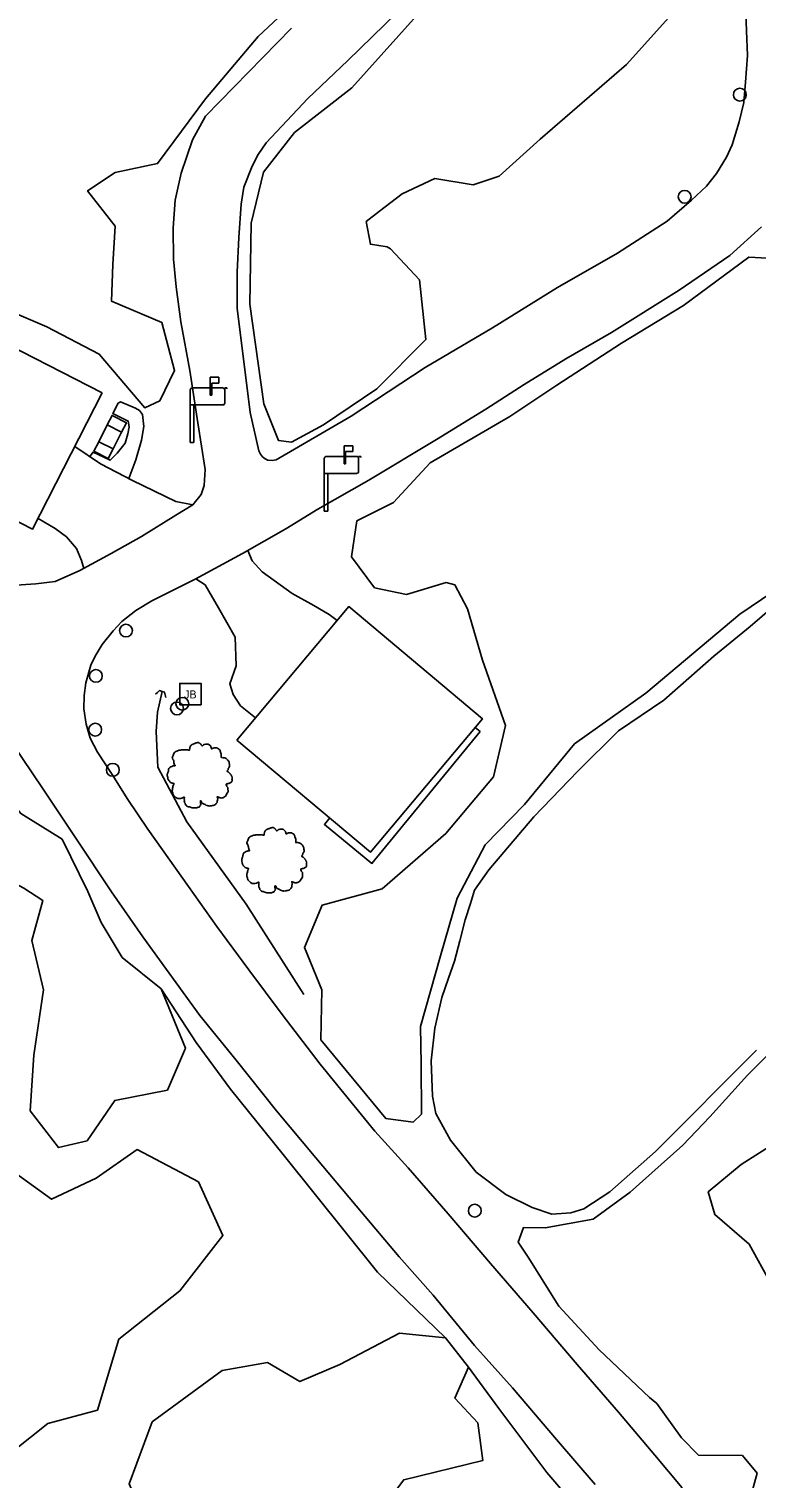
# Model space of a CAD drawing. Extents: x 2160437 to 2172832, y 205694 to 212444.
# Drawn here: x 2171429.7 to 2171600, y 207128.5 to 207468 of the extents above; entities that cross this region are included whole.
import ezdxf

# ---------------------------------------------------------------- set-up
doc = ezdxf.new("R2010")
doc.units = 0
for name, color, linetype in [('Default', 7, 'Continuous'), ('RD_EX_Bldg', 7, 'Continuous'), ('RD_EX_BldgApp', 7, 'Continuous'), ('RD_EX_Conc', 7, 'Continuous'), ('RD_EX_DR_Culvert', 7, 'Continuous'), ('RD_EX_DR_Inlet', 7, 'Continuous'), ('RD_EX_Driveway', 7, 'Continuous'), ('RD_EX_H2O_Ditch', 7, 'Continuous'), ('RD_EX_H2O_Pond', 7, 'Continuous'), ('RD_EX_Road', 7, 'Continuous'), ('RD_EX_Road_Post', 7, 'Continuous'), ('RD_EX_VEG', 7, 'Continuous'), ('RD_EX_VEG_ShrubLine', 7, 'Continuous'), ('RD_EX_VEG_TreeLine', 7, 'Continuous')]:
    doc.layers.add(name, color=color, linetype=linetype)

# ---------------------------------------------------------------- blocks, each defined once
blk = doc.blocks.new('CB')
at = {"layer": 'Default'}
blk.add_lwpolyline([(0.036, -0.042), (0.018, -0.031), (0, -0.021), (0, 0), (0, 0.021), (0.018, 0.031), (0.036, 0.042)], dxfattribs=at)
blk = doc.blocks.new('POST')
at = {"layer": 'Default'}
for start, end in [(90, 270), (270, 90)]:
    blk.add_arc((0, 0), 0.0417, start, end, dxfattribs=at)
blk = doc.blocks.new('T2')
at = {"layer": 'RD_EX_VEG'}
for points in [[(0.05, 7.21), (-0.25, 7.24), (-0.57, 7.14), (-0.82, 7.04), (-1.05, 6.96), (-1.27, 6.86), (-1.57, 6.69), (-1.8, 6.49), (-1.92, 6.24), (-1.97, 6.01), (-2.02, 5.74), (-2.02, 5.56), (-2.15, 5.54), (-2.3, 5.56), (-2.55, 5.64), (-2.8, 5.64), (-3.05, 5.64), (-3.4, 5.61), (-3.75, 5.61), (-4.02, 5.56), (-4.35, 5.51), (-4.72, 5.39), (-5.07, 5.26), (-5.37, 5.01), (-5.62, 4.54), (-5.75, 4.19), (-5.9, 3.94), (-5.75, 3.49), (-5.57, 3.14), (-5.55, 2.94), (-5.47, 2.52), (-5.37, 2.29), (-5.25, 2.09), (-5.32, 2.07), (-5.7, 2.02), (-6, 1.92), (-6.42, 1.69), (-6.64, 1.47), (-6.74, 1.14), (-6.77, 0.79), (-6.87, 0.59), (-6.94, 0.32), (-6.97, 0.24), (-7.02, -0.08), (-6.92, -0.53), (-6.89, -0.88), (-6.77, -1.11), (-6.62, -1.28), (-6.44, -1.53), (-6.05, -1.76), (-5.72, -1.86), (-5.52, -1.88), (-5.7, -2.38), (-5.75, -2.73), (-5.87, -3.13), (-5.87, -3.21), (-5.92, -3.68), (-5.77, -4.01), (-5.7, -4.38), (-5.52, -4.61), (-5.25, -4.91), (-4.92, -5.13), (-4.42, -5.26), (-4.02, -5.23), (-3.45, -5.06), (-3.2, -4.98), (-3.22, -5.16), (-3.2, -5.53), (-3.2, -5.96), (-3.05, -6.28), (-2.95, -6.56), (-2.8, -6.81), (-2.47, -7.03), (-2.07, -7.11), (-1.65, -7.26), (-1.2, -7.33), (-0.7, -7.36), (-0.1, -7.21), (0.18, -7.08), (0.28, -6.91), (0.48, -6.53), (0.43, -6.31), (0.45, -5.71), (0.55, -5.88), (0.73, -6.23), (1.23, -6.53), (1.63, -6.71), (2.1, -6.86), (2.4, -6.93), (2.88, -6.86), (3.25, -6.78), (3.63, -6.66), (3.93, -6.38), (4.1, -6.11), (4.15, -5.83), (4.23, -5.46), (4.28, -5.28)], [(4.28, -5.28), (4.2, -5.11), (4.15, -4.86), (4.23, -4.88), (4.4, -4.93), (4.68, -5.06), (4.9, -5.13), (5.23, -5.11), (5.5, -5.01), (5.95, -4.73), (6.22, -4.26), (6.5, -3.86), (6.57, -3.53), (6.52, -3.31), (6.5, -2.81), (6.3, -2.56), (6.25, -2.43), (6.15, -2.03), (6.22, -1.98), (6.5, -1.93), (6.87, -1.81), (7.15, -1.68), (7.37, -1.51), (7.45, -1.28), (7.42, -0.88), (7.47, -0.48), (7.4, -0.33), (7.3, -0.18), (7.22, 0.02), (7.07, 0.17), (6.97, 0.32), (6.87, 0.42), (6.75, 0.57), (6.57, 0.69), (6.42, 0.74), (6.37, 0.89), (6.52, 1.09), (6.57, 1.19), (6.6, 1.42), (6.82, 1.77), (6.87, 2.17), (6.82, 2.59), (6.77, 2.87), (6.62, 3.14), (6.42, 3.39), (6.3, 3.56), (6.12, 3.69), (5.8, 3.81), (5.55, 3.86), (5.2, 3.86), (5, 3.91), (5.03, 3.96), (5.03, 4.11), (5.03, 4.39), (4.95, 4.84), (4.8, 5.34), (4.8, 5.36), (4.7, 5.61), (4.48, 5.81), (4.3, 5.91), (4.1, 6.04), (3.85, 6.06), (3.55, 6.06), (3.28, 6.01), (3.08, 5.91), (2.9, 5.79), (2.83, 5.94), (2.73, 6.24), (2.68, 6.39), (2.53, 6.56), (2.3, 6.76), (1.85, 6.89), (1.23, 6.81), (0.93, 6.61), (0.78, 6.44), (0.73, 6.56), (0.53, 6.76), (0.43, 6.94), (0.25, 7.06), (0.1, 7.16), (0, 7.21)]]:
    blk.add_spline(points, degree=3, dxfattribs=at)

msp = doc.modelspace()

# ---------------------------------------------------------------- linework, layer by layer
at = {"layer": 'RD_EX_Bldg'}
for points in [[(2171446.83, 207382.74), (2171430.51, 207350.85), (2171389.43, 207371.87), (2171405.74, 207403.76)], [(2171478.36, 207301.4), (2171504.58, 207332.66), (2171535.89, 207306.4), (2171509.68, 207275.14)]]:
    msp.add_lwpolyline(points, close=True, dxfattribs=at)
at = {"layer": 'RD_EX_BldgApp'}
for p, q in [((2171472.07, 207386.39), (2171474.13, 207386.39)), ((2171472.07, 207382.2), (2171472.07, 207386.39)), ((2171474.13, 207385.04), (2171472.45, 207385.04)), ((2171472.45, 207385.04), (2171472.45, 207382.2)), ((2171474.13, 207386.39), (2171474.13, 207385.04)), ((2171467.43, 207379.91), (2171467.43, 207383.41)), ((2171467.93, 207383.91), (2171475, 207383.91)), ((2171472.45, 207382.2), (2171472.07, 207382.2)), ((2171475.5, 207383.41), (2171475.5, 207383.91)), ((2171475.5, 207383.91), (2171476, 207383.91)), ((2171475.5, 207383.41), (2171475.5, 207380.41)), ((2171476, 207383.91), (2171476, 207383.66)), ((2171467.43, 207379.91), (2171467.43, 207371.09)), ((2171475, 207379.91), (2171467.43, 207379.91)), ((2171468.27, 207379.91), (2171468.27, 207371.09)), ((2171467.43, 207371.09), (2171468.27, 207371.09)), ((2171503.46, 207370.34), (2171505.51, 207370.34)), ((2171503.46, 207366.15), (2171503.46, 207370.34)), ((2171505.51, 207368.99), (2171503.84, 207368.99)), ((2171503.84, 207368.99), (2171503.84, 207366.15)), ((2171505.51, 207370.34), (2171505.51, 207368.99)), ((2171498.81, 207363.86), (2171498.81, 207367.36)), ((2171499.31, 207367.86), (2171506.38, 207367.86)), ((2171503.84, 207366.15), (2171503.46, 207366.15)), ((2171506.88, 207367.36), (2171506.88, 207367.86)), ((2171506.88, 207367.86), (2171507.38, 207367.86)), ((2171506.88, 207367.36), (2171506.88, 207364.36)), ((2171507.38, 207367.86), (2171507.38, 207367.61)), ((2171498.81, 207363.86), (2171498.81, 207355.04)), ((2171506.38, 207363.86), (2171498.81, 207363.86)), ((2171499.65, 207363.86), (2171499.65, 207355.04)), ((2171498.81, 207355.04), (2171499.65, 207355.04))]:
    msp.add_line(p, q, dxfattribs=at)
for points in [[(2171447.98, 207375.24), (2171451.35, 207373.53), (2171449.37, 207369.61), (2171445.99, 207371.31)], [(2171447.98, 207375.24), (2171451.35, 207373.53), (2171452.47, 207375.74), (2171449.1, 207377.45)], [(2171445.99, 207371.31), (2171449.37, 207369.61), (2171448.24, 207367.38), (2171444.87, 207369.09)]]:
    msp.add_lwpolyline(points, close=True, dxfattribs=at)
for points in [[(2171534.17, 207304.34), (2171535.33, 207303.39)], [(2171535.33, 207303.39), (2171509.99, 207272.49), (2171498.85, 207281.63), (2171500.11, 207283.17)]]:
    msp.add_lwpolyline(points, dxfattribs=at)
for centre, start, end in [((2171467.93, 207383.41), 90, 180), ((2171475, 207383.41), 360, 90), ((2171475, 207380.41), 270, 0), ((2171499.31, 207367.36), 90, 180), ((2171506.38, 207367.36), 360, 90), ((2171506.38, 207364.36), 270, 0)]:
    msp.add_arc(centre, 0.5, start, end, dxfattribs=at)
at = {"layer": 'RD_EX_Conc'}
msp.add_lwpolyline([(2171443.93, 207367.81), (2171444.68, 207368.89), (2171448.7, 207366.96), (2171450.31, 207368.59), (2171452.18, 207370.97), (2171452.83, 207373.17), (2171453.13, 207374.77), (2171452.89, 207376.13), (2171449.26, 207377.88), (2171450.51, 207380.37), (2171451.07, 207380.65), (2171454.58, 207379.13), (2171455.51, 207378.6), (2171456.22, 207377.64), (2171456.57, 207374.87), (2171455.99, 207371.67), (2171454.68, 207367.04), (2171453.04, 207362.65)], dxfattribs=at)
at = {"layer": 'RD_EX_DR_Inlet'}
msp.add_line((2171469.96, 207309.68), (2171469.96, 207314.68), dxfattribs=at)
msp.add_lwpolyline([(2171469.96, 207309.68), (2171469.96, 207314.68), (2171464.96, 207314.68), (2171464.96, 207309.68)], close=True, dxfattribs=at)
at = {"layer": 'RD_EX_Driveway'}
for points in [[(2171468, 207356.5), (2171464.04, 207357.32), (2171453.93, 207362.18), (2171446.4, 207366.11), (2171440.42, 207370.22)], [(2171442.48, 207341.6), (2171441.99, 207343.51), (2171440.75, 207346.25), (2171438.43, 207349.03), (2171435.78, 207350.98), (2171431.78, 207353.33)], [(2171480.91, 207345.79), (2171481.91, 207343.38), (2171484.26, 207340.82), (2171491.32, 207335.75), (2171496.35, 207332.93), (2171499.95, 207330.83), (2171501.89, 207329.45)], [(2171468.72, 207339.2), (2171470.95, 207337.74), (2171474.07, 207332.39), (2171477.92, 207325.52), (2171478.16, 207318.83), (2171476.71, 207314.57), (2171477.48, 207312.09), (2171479.17, 207309.43), (2171482.74, 207306.62)]]:
    msp.add_lwpolyline(points, dxfattribs=at)
at = {"layer": 'RD_EX_H2O_Ditch'}
msp.add_lwpolyline([(2171494.01, 207241.77), (2171480.53, 207262.98), (2171466.6, 207282.21), (2171459.84, 207295.05), (2171459.41, 207303.4), (2171459.79, 207307.92), (2171460.82, 207312.8)], dxfattribs=at)
at = {"layer": 'RD_EX_H2O_Pond'}
msp.add_lwpolyline([(2171600.08, 207228.72), (2171576.41, 207204.98), (2171565.72, 207195.53), (2171559.63, 207191.57), (2171556.56, 207190.65), (2171552.16, 207190.34), (2171547.5, 207191.92), (2171541.37, 207194.94), (2171534.39, 207200.19), (2171528.37, 207207.63), (2171524.95, 207213.88), (2171524.18, 207217.94), (2171523.87, 207226.21), (2171524.77, 207233.92), (2171526.4, 207241.09), (2171527.96, 207245.6), (2171529.36, 207249.63), (2171530.57, 207254.36), (2171531.83, 207259.31), (2171533.05, 207263.07), (2171534, 207266.23), (2171537.36, 207270.99), (2171547.92, 207283.45), (2171558.24, 207294.08), (2171567.74, 207303.58), (2171578.35, 207310.73), (2171590.09, 207321.02), (2171598.64, 207328.01), (2171607.01, 207335.28)], dxfattribs=at)
at = {"layer": 'RD_EX_Road'}
for points in [[(2171530.12, 207485.76), (2171504.37, 207460.59), (2171495, 207451.72), (2171485.18, 207441.31), (2171483.34, 207438.63), (2171481.97, 207435.88), (2171480, 207430.92), (2171479.37, 207426.92), (2171478.78, 207419.12), (2171478.43, 207411.02), (2171478.43, 207402.57), (2171481.45, 207378.12), (2171483.5, 207369.16), (2171483.88, 207368.36), (2171484.37, 207367.74), (2171484.95, 207367.3), (2171485.58, 207367.01), (2171486.66, 207366.88), (2171487.57, 207367.03), (2171505.1, 207377.3), (2171522.43, 207388.66), (2171538.23, 207397.95), (2171553.51, 207407.44), (2171567.55, 207415.49), (2171579.13, 207423), (2171584.83, 207427.88), (2171588.34, 207431.21), (2171590.75, 207434.17), (2171593.07, 207438), (2171594.38, 207440.85), (2171596.06, 207446.22), (2171597.1, 207450.74), (2171597.49, 207455.51), (2171598, 207461.81), (2171597.74, 207467.54), (2171597.55, 207473.95)], [(2171491.13, 207468.22), (2171471.04, 207447.57), (2171467.98, 207442.02), (2171465.33, 207434.23), (2171463.92, 207427.9), (2171463.46, 207421.43), (2171463.53, 207414.08), (2171464.14, 207407.58), (2171465.2, 207399.38), (2171467.3, 207388), (2171469.2, 207375.75), (2171470.93, 207364.82), (2171470.71, 207361.04), (2171469.98, 207358.96), (2171468.02, 207356.51), (2171464.05, 207354.12), (2171456.02, 207349.08), (2171448.87, 207345.08), (2171441.55, 207341.09), (2171435.77, 207338.57), (2171431.25, 207338), (2171425.5, 207337.6)], [(2171582.69, 207126.23), (2171576.25, 207133.86), (2171576.25, 207133.86), (2171567.77, 207143.91), (2171558.07, 207155.07), (2171547.77, 207167.18), (2171537.81, 207178.8), (2171527.84, 207190.36), (2171518.52, 207201.18), (2171510.7, 207209.78), (2171497.84, 207225.49), (2171488.97, 207237.12), (2171481.14, 207247.53), (2171473.65, 207257.73), (2171465.68, 207268.94), (2171457.52, 207280.56), (2171452.81, 207287.5), (2171449.12, 207293.34), (2171445.67, 207298.53), (2171444.02, 207301.88), (2171443.01, 207305.11), (2171442.53, 207308.71), (2171442.54, 207311.81), (2171442.97, 207314.83), (2171444.13, 207318.97), (2171445.12, 207321.06), (2171446.83, 207323.8), (2171449.35, 207327.01), (2171451.44, 207329.17), (2171454.66, 207331.75), (2171458.45, 207334.04), (2171468.59, 207339.13), (2171479.69, 207345.09), (2171489.79, 207350.88), (2171497.29, 207355.48), (2171509.27, 207362.26), (2171525.16, 207371.83), (2171536.66, 207378.91), (2171545.67, 207384.69), (2171555.39, 207390.75), (2171566.14, 207396.86), (2171581.99, 207406.82), (2171593.86, 207414.95), (2171601.3, 207421.64)], [(2171425.53, 207300.93), (2171433.01, 207289.87), (2171440.6, 207278.38), (2171449, 207265.85), (2171456.3, 207255.33), (2171469.67, 207236.87), (2171469.67, 207236.87), (2171478.22, 207226.43), (2171487.63, 207214.54), (2171496.84, 207203.54), (2171506.3, 207192.26), (2171516.39, 207180.35), (2171524.32, 207171.37), (2171534, 207159.58), (2171542.93, 207149.63), (2171553.25, 207137.55), (2171562.31, 207126.95)]]:
    msp.add_lwpolyline(points, dxfattribs=at)
at = {"layer": 'RD_EX_VEG_ShrubLine'}
for points in [[(2171460.58, 207243.08), (2171468.81, 207230.57), (2171476.9, 207219.57), (2171489.22, 207204.29), (2171511.28, 207176.71), (2171527.21, 207161.36)], [(2171532.6, 207154.5), (2171539.69, 207144.82), (2171550.96, 207129.8), (2171561.12, 207117.96)]]:
    msp.add_lwpolyline(points, dxfattribs=at)
at = {"layer": 'RD_EX_VEG_TreeLine'}
for points in [[(2171510.74, 207491.92), (2171483.32, 207466.26), (2171471.02, 207451.61), (2171459.78, 207436.47), (2171449.85, 207434.41), (2171443.38, 207430.11), (2171449.82, 207421.8), (2171449.33, 207412.83), (2171449, 207404.22), (2171460.81, 207399.21), (2171463.78, 207388.01), (2171460.28, 207380.85), (2171456.77, 207379.26), (2171446.12, 207391.82), (2171433.84, 207398.19), (2171416.8, 207405.52)], [(2171583.1, 207474.56), (2171569.67, 207459.71), (2171549.43, 207442.21), (2171539.84, 207433.52), (2171533.72, 207431.46), (2171524.75, 207432.95), (2171517.1, 207429.36), (2171511.79, 207425.3), (2171508.64, 207422.89), (2171509.64, 207417.55), (2171513.54, 207416.98), (2171514.34, 207416.51), (2171521.14, 207409.22), (2171522.63, 207395.23), (2171511.11, 207383.66), (2171498.63, 207375.29), (2171491.16, 207371.21), (2171488.09, 207371.6), (2171484.64, 207380.2), (2171481.36, 207403.55), (2171481.74, 207422.47), (2171484.61, 207434.45), (2171491.82, 207443.73), (2171505.27, 207454.2), (2171523.17, 207474.1)], [(2171609.03, 207339.53), (2171596.22, 207330.89), (2171574.2, 207312.38), (2171557.45, 207300.49), (2171545.73, 207286.28), (2171536.54, 207276.89), (2171529.97, 207264.38), (2171526.07, 207250.83), (2171521.41, 207234.29), (2171521.53, 207225.5), (2171521.62, 207213.78), (2171519.62, 207211.86), (2171513.23, 207212.76), (2171498.02, 207231.14), (2171498.26, 207242.91), (2171494.18, 207252.81), (2171498.32, 207262.69), (2171512.39, 207266.57), (2171527.29, 207279.53), (2171538.46, 207292.77), (2171541.25, 207304.79), (2171535.92, 207320.14), (2171532.4, 207332.13), (2171529.41, 207337.77), (2171527.41, 207338.28), (2171518.12, 207335.54), (2171510.6, 207337.08), (2171505.21, 207344.33), (2171506.46, 207352.79), (2171515.03, 207357.08), (2171523.65, 207366.32), (2171542.29, 207377.24), (2171553.28, 207384.58), (2171568.44, 207394.36), (2171582.98, 207403.21), (2171598.26, 207414.57), (2171607.07, 207414.07)], [(2171600.22, 207129.6), (2171596.78, 207133.75), (2171586.48, 207133.89), (2171582.56, 207137.94), (2171576.74, 207145.96), (2171575.06, 207147.33), (2171563.22, 207158.55), (2171553.81, 207168.76), (2171546.57, 207180.22), (2171544.24, 207183.75), (2171545.52, 207187.23), (2171550.61, 207187.13), (2171561.8, 207189.15), (2171570.5, 207195.51), (2171582.83, 207206.52), (2171589.18, 207213.11), (2171597.95, 207222.87), (2171605.48, 207230.42)], [(2171361.09, 207126.77), (2171368.51, 207138), (2171360.06, 207150.55), (2171365.9, 207162.08), (2171372.51, 207165.99), (2171370.84, 207177.45), (2171376.25, 207186.19), (2171389.35, 207197.7), (2171406.4, 207195.73), (2171416.35, 207201.1), (2171426.52, 207199.95), (2171434.93, 207193.83), (2171445.42, 207198.74), (2171455.02, 207205.44), (2171469.39, 207197.86), (2171475.1, 207185.36), (2171464.96, 207172.34), (2171450.68, 207161.05), (2171445.69, 207144.43), (2171434.1, 207141.31), (2171426, 207134.88), (2171414.8, 207127.95)], [(2171604.83, 207207.24), (2171596.52, 207201.97), (2171588.78, 207195.59), (2171590.35, 207190.23), (2171598.4, 207183.32), (2171603.44, 207174.05)], [(2171598.12, 207122.01), (2171600.22, 207129.6)]]:
    msp.add_lwpolyline(points, dxfattribs=at)
for points in [[(2171424.01, 207269.1), (2171415.62, 207270.61), (2171408.92, 207279.04), (2171408.68, 207286.42), (2171413.09, 207293.69), (2171419.86, 207294), (2171427.74, 207284.17), (2171437.41, 207278.22), (2171443.41, 207265.95), (2171446.56, 207258.62), (2171451.48, 207250.48), (2171460.58, 207243.08), (2171466.29, 207229.23), (2171462.09, 207219.4), (2171449.74, 207216.96), (2171443.27, 207207.53), (2171436.54, 207205.92), (2171429.91, 207214.53), (2171430.79, 207227.6), (2171433.03, 207242.92), (2171430.31, 207254.44), (2171432.92, 207263.82), (2171428.48, 207266.72), (2171425.56, 207268.28)], [(2171474.7, 207108.12), (2171459.43, 207112.36), (2171453.09, 207127.15), (2171458.48, 207141.66), (2171474.91, 207153.67), (2171485.5, 207155.53), (2171493.08, 207151.09), (2171502.51, 207155.09), (2171516.48, 207162.45), (2171527.21, 207161.36), (2171532.6, 207154.5), (2171529.45, 207147.18), (2171534.81, 207141.4), (2171536.01, 207132.62), (2171517.46, 207128.1), (2171506.13, 207113), (2171497.21, 207101.28), (2171490.38, 207100.15), (2171482.44, 207102.63), (2171478.6, 207107.07), (2171475.14, 207107.7)]]:
    msp.add_lwpolyline(points, close=True, dxfattribs=at)

# ---------------------------------------------------------------- block references
at = {"layer": 'RD_EX_DR_Culvert', "xscale": 30, "yscale": 30, "rotation": -108.02831900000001}
msp.add_blockref('CB', (2171460.82, 207312.8), dxfattribs=at)
at = {"layer": 'RD_EX_Road_Post', "xscale": 36, "yscale": 36}
for p in [(2171596.19, 207452.61), (2171583.28, 207428.69), (2171452.37, 207327.05), (2171445.32, 207316.43), (2171464.32, 207308.81), (2171465.56, 207309.91), (2171445.17, 207303.85), (2171449.29, 207294.42), (2171534.09, 207191.14)]:
    msp.add_blockref('POST', p, dxfattribs=at)
at = {"layer": 'RD_EX_VEG', "xscale": 1.0499999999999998, "yscale": 1.0499999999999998}
for p in [(2171469.41, 207293.22), (2171486.87, 207273.31)]:
    msp.add_blockref('T2', p, dxfattribs=at)

# ---------------------------------------------------------------- texts
at = {"layer": 'RD_EX_DR_Inlet'}
msp.add_text('JB', height=1.875, dxfattribs=at).set_placement((2171465.99, 207311.16))

doc.saveas('drawing.dxf')
